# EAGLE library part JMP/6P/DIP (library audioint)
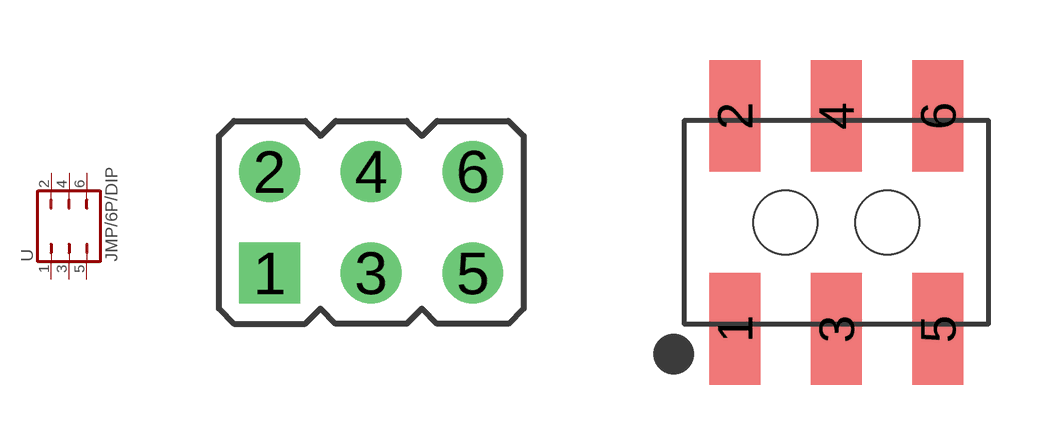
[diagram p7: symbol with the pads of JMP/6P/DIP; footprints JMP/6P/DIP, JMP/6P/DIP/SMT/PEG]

Designator prefix -

## JMP/6P/DIP  [JMP/6P/DIP]
1  1  pas
2  2  pas
3  3  pas
4  4  pas
5  5  pas
6  6  pas

## JMP/6P/DIPSMT/PEG  [JMP/6P/DIP/SMT/PEG]
Pads as for JMP/6P/DIP

## Footprint JMP/6P/DIP (pad centres in mm)
drill 0.914 pad 1.524 square: 1 -2.54,-1.27
drill 0.914 pad 1.524 round: 2 -2.54,1.27; 3 0,-1.27; 4 0,1.27; 5 2.54,-1.27; 6 2.54,1.27

## Footprint JMP/6P/DIP/SMT/PEG (pad centres in mm)
smd 1.27 x 2.794: 1 -2.54,-2.667; 2 -2.54,2.667; 3 0,-2.667; 4 0,2.667; 5 2.54,-2.667; 6 2.54,2.667
hole 1.6 at -1.27,0
hole 1.6 at 1.27,0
